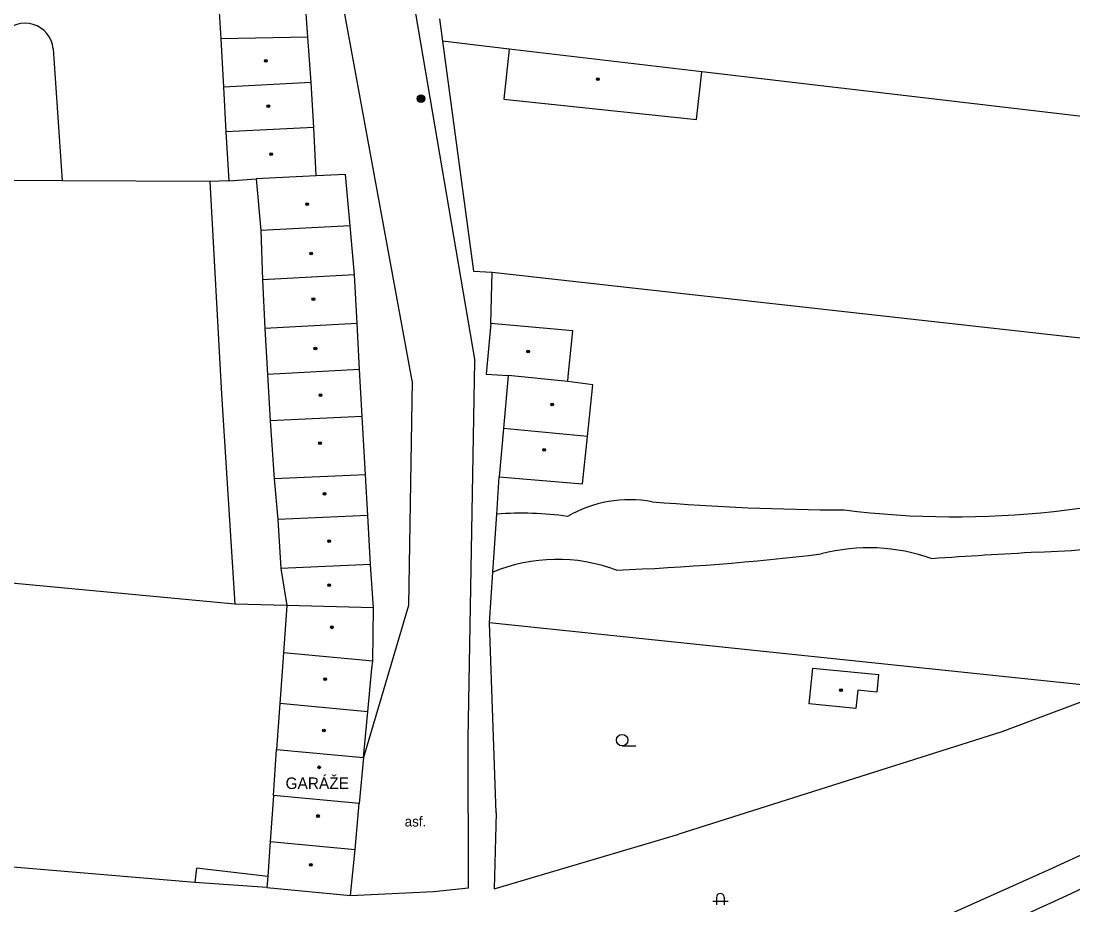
# Model space of a CAD drawing. Extents: x -596024 to -594475, y -1163820 to -1161957.
# Drawn here: x -595951 to -595882.6, y -1163179.9 to -1163122.3 of the extents above; entities that cross this region are included whole.
import ezdxf

# ---------------------------------------------------------------- set-up
doc = ezdxf.new("R2010")
doc.units = 0
for name, color, linetype in [('Level 10', 7, 'Continuous'), ('Level 11', 7, 'Continuous'), ('Level 25', 7, 'Continuous'), ('Level 36', 7, 'Continuous'), ('Level 39', 7, 'Continuous'), ('Level 40', 7, 'Continuous'), ('Level 41', 7, 'Continuous'), ('Level 5', 7, 'Continuous'), ('Level 7', 7, 'Continuous')]:
    doc.layers.add(name, color=color, linetype=linetype)

msp = doc.modelspace()

# ---------------------------------------------------------------- linework, layer by layer
at = {"layer": 'Level 10'}
for points in [[(-595925.56, -1163145.76), (-595930.74, -1163117.5)], [(-595929.58, -1163179.24), (-595924.17, -1163178.97), (-595921.89, -1163178.75), (-595921.92, -1163169.04), (-595921.49, -1163144.47)], [(-595925.56, -1163145.76), (-595925.81, -1163160.38), (-595928.73, -1163170.27)]]:
    msp.add_lwpolyline(points, dxfattribs=at)
at = {"layer": 'Level 11'}
for points in [[(-595733.15, -1163057.32), (-595759.5, -1163089.99), (-595778.37, -1163109.17), (-595795.84, -1163125.04), (-595814.68, -1163140.46), (-595836.38, -1163155.41), (-595857.69, -1163167.34), (-595883.05, -1163179.29), (-595896.6, -1163185.46), (-595919.59, -1163194.75), (-595919.36, -1163195.51)], [(-595920.12, -1163192.61), (-595897.38, -1163183.5), (-595884.17, -1163177.56), (-595867.38, -1163169.87), (-595837.49, -1163153.6), (-595815.9, -1163138.63), (-595797.14, -1163123.28), (-595781.78, -1163109.18), (-595766.48, -1163093.71), (-595763.38, -1163090.58), (-595762.22, -1163089.18), (-595761.3, -1163088.06)], [(-595925.77, -1163119.3), (-595921.49, -1163144.47)], [(-595923.78, -1163122.2), (-595923.58, -1163123.66), (-595921.57, -1163138.62), (-595920.36, -1163138.68)], [(-595948.92, -1163124.15), (-595948.33, -1163132.74)], [(-595856.82, -1163131.52), (-595871.99, -1163129.73), (-595880.33, -1163128.75), (-595906.73, -1163125.64), (-595919.26, -1163124.17), (-595923.58, -1163123.66)], [(-595919.26, -1163124.17), (-595919.6, -1163127.42), (-595907.06, -1163128.76), (-595906.73, -1163125.64)], [(-595920.36, -1163138.68), (-595849.07, -1163146.65), (-595837.48, -1163146.72)], [(-595879.71, -1163165.77), (-595920.53, -1163161.49)], [(-595920.1, -1163173.87), (-595920.22, -1163178.81), (-595908.22, -1163175.26)]]:
    msp.add_lwpolyline(points, dxfattribs=at)
for centre, radius, start, end in [((-595950.742, -1163124.316), 1.83, 5.21471, 140.80364), ((-595890.23, -1163096.703), 57.901, 262.81706, 289.89133), ((-595911.417, -1163161.507), 8.021, 79.53376, 120.26819), ((-595896.955, -1162994.59), 159.561, 265.3251, 269.81525), ((-595918.424, -1163174.864), 20.5, 81.68697, 94.57767), ((-595889.494, -1163056.561), 100.456, 272.63844, 280.63793), ((-595918.739, -1162992.496), 165.7, 272.23405, 276.85912), ((-595895.87, -1163168.881), 12.264, 70.36704, 104.54335), ((-595866.178, -1163519.66), 363.232, 92.94973, 94.03701), ((-595916.131, -1163168.287), 10.918, 69.34866, 112.50633)]:
    msp.add_arc(centre, radius, start, end, dxfattribs=at)
at = {"layer": 'Level 25'}
for radius in [0.25, 0.2, 0.15, 0.1, 0.05]:
    msp.add_circle((-595924.99, -1163127.4), radius, dxfattribs=at)
at = {"layer": 'Level 36'}
for p, q in [((-595911.9, -1163169.505), (-595911.025, -1163169.505)), ((-595906.016, -1163179.606), (-595905.016, -1163179.606)), ((-595905.766, -1163179.356), (-595905.766, -1163179.856)), ((-595905.266, -1163179.356), (-595905.266, -1163179.856))]:
    msp.add_line(p, q, dxfattribs=at)
msp.add_circle((-595911.9, -1163169.13), 0.375, dxfattribs=at)
msp.add_arc((-595905.516, -1163179.356), 0.25, 0, 180, dxfattribs=at)
at = {"layer": 'Level 39'}
for centre, radius in [((-595935.09, -1163124.93), 0.09), ((-595935.09, -1163124.93), 0.0398), ((-595913.48, -1163126.13), 0.09), ((-595913.48, -1163126.13), 0.0398), ((-595934.92, -1163127.88), 0.09), ((-595934.92, -1163127.88), 0.0398), ((-595934.74, -1163131.01), 0.09), ((-595934.74, -1163131.01), 0.0398), ((-595932.39, -1163134.26), 0.09), ((-595932.39, -1163134.26), 0.0398), ((-595932.13, -1163137.47), 0.09), ((-595932.13, -1163137.47), 0.0398), ((-595931.99, -1163140.44), 0.09), ((-595931.99, -1163140.44), 0.0398), ((-595931.86, -1163143.65), 0.09), ((-595931.86, -1163143.65), 0.0398), ((-595918.02, -1163143.84), 0.09), ((-595918.02, -1163143.84), 0.0398), ((-595931.52, -1163146.69), 0.09), ((-595931.52, -1163146.69), 0.0398), ((-595916.46, -1163147.29), 0.09), ((-595916.46, -1163147.29), 0.0398), ((-595931.56, -1163149.81), 0.09), ((-595931.56, -1163149.81), 0.0398), ((-595916.97, -1163150.24), 0.09), ((-595916.97, -1163150.24), 0.0398), ((-595931.26, -1163153.11), 0.09), ((-595931.26, -1163153.11), 0.0398), ((-595930.96, -1163156.19), 0.09), ((-595930.96, -1163156.19), 0.0398), ((-595930.96, -1163159.05), 0.09), ((-595930.96, -1163159.05), 0.0398), ((-595930.79, -1163161.79), 0.09), ((-595930.79, -1163161.79), 0.0398), ((-595931.22, -1163165.17), 0.09), ((-595931.22, -1163165.17), 0.0398), ((-595897.67, -1163165.88), 0.09), ((-595897.67, -1163165.88), 0.0398), ((-595931.31, -1163168.51), 0.09), ((-595931.31, -1163168.51), 0.0398), ((-595931.61, -1163170.9), 0.09), ((-595931.61, -1163170.9), 0.0398), ((-595931.69, -1163174.07), 0.09), ((-595931.69, -1163174.07), 0.0398), ((-595932.16, -1163177.24), 0.09), ((-595932.16, -1163177.24), 0.0398)]:
    msp.add_circle(centre, radius, dxfattribs=at)
at = {"layer": 'Level 5'}
for points in [[(-595938.19, -1163120.71), (-595938.02, -1163123.5)], [(-595932.35, -1163123.39), (-595932.55, -1163120.59)], [(-595932.35, -1163123.39), (-595938.02, -1163123.5)], [(-595938.02, -1163123.5), (-595937.84, -1163126.65)], [(-595932.13, -1163126.34), (-595932.35, -1163123.39)], [(-595932.13, -1163126.34), (-595937.84, -1163126.65)], [(-595937.84, -1163126.65), (-595937.68, -1163129.56)], [(-595931.97, -1163129.26), (-595932.13, -1163126.34)], [(-595931.97, -1163129.26), (-595937.68, -1163129.56)], [(-595937.68, -1163129.56), (-595937.5, -1163132.73)], [(-595931.81, -1163132.41), (-595931.97, -1163129.26)], [(-595931.81, -1163132.41), (-595935.71, -1163132.6)], [(-595929.89, -1163132.32), (-595931.81, -1163132.41)], [(-595929.6, -1163135.67), (-595929.89, -1163132.32)], [(-595937.5, -1163132.73), (-595935.71, -1163132.6)], [(-595935.71, -1163132.6), (-595935.41, -1163135.98)], [(-595929.6, -1163135.67), (-595935.41, -1163135.98)], [(-595929.32, -1163138.86), (-595929.6, -1163135.67)], [(-595935.41, -1163135.98), (-595935.31, -1163139.19)], [(-595929.32, -1163138.86), (-595935.31, -1163139.19)], [(-595935.31, -1163139.19), (-595935.14, -1163142.34)], [(-595929.14, -1163142.02), (-595929.32, -1163138.86)], [(-595929.14, -1163142.02), (-595935.14, -1163142.34)], [(-595928.98, -1163145.01), (-595929.14, -1163142.02)], [(-595920.45, -1163142.03), (-595920.76, -1163145.31)], [(-595915.11, -1163142.49), (-595920.45, -1163142.03)], [(-595935.14, -1163142.34), (-595934.97, -1163145.34)], [(-595915.41, -1163145.47), (-595915.11, -1163142.49)], [(-595928.98, -1163145.01), (-595934.97, -1163145.34)], [(-595934.97, -1163145.34), (-595934.8, -1163148.35)], [(-595928.81, -1163148.08), (-595928.98, -1163145.01)], [(-595920.76, -1163145.31), (-595919.32, -1163145.4)], [(-595919.32, -1163145.4), (-595919.62, -1163148.86)], [(-595915.44, -1163145.8), (-595919.32, -1163145.4)], [(-595915.44, -1163145.8), (-595915.41, -1163145.47)], [(-595913.82, -1163146.01), (-595915.44, -1163145.8)], [(-595914.16, -1163149.37), (-595913.82, -1163146.01)], [(-595928.81, -1163148.08), (-595934.8, -1163148.35)], [(-595928.6, -1163151.87), (-595928.81, -1163148.08)], [(-595934.8, -1163148.35), (-595934.54, -1163152.14)], [(-595919.62, -1163148.86), (-595919.9, -1163152.01)], [(-595914.16, -1163149.37), (-595919.62, -1163148.86)], [(-595914.48, -1163152.46), (-595914.16, -1163149.37)], [(-595928.6, -1163151.87), (-595934.54, -1163152.14)], [(-595934.54, -1163152.14), (-595934.3, -1163154.78)], [(-595928.45, -1163154.51), (-595928.6, -1163151.87)], [(-595919.9, -1163152.01), (-595914.48, -1163152.46)], [(-595928.45, -1163154.51), (-595934.3, -1163154.78)], [(-595934.3, -1163154.78), (-595934.11, -1163157.97)], [(-595928.28, -1163157.7), (-595928.45, -1163154.51)], [(-595928.28, -1163157.7), (-595934.11, -1163157.97)], [(-595928.09, -1163160.53), (-595928.28, -1163157.7)], [(-595934.11, -1163157.97), (-595933.72, -1163160.38)], [(-595933.72, -1163160.38), (-595933.94, -1163163.46)], [(-595928.09, -1163160.53), (-595933.72, -1163160.38)], [(-595928.13, -1163164), (-595928.09, -1163160.53)], [(-595933.94, -1163163.46), (-595934.17, -1163166.75)], [(-595928.13, -1163164), (-595933.94, -1163163.46)], [(-595928.45, -1163167.29), (-595928.18, -1163164.47)], [(-595928.18, -1163164.47), (-595928.13, -1163164)], [(-595899.74, -1163166.78), (-595899.51, -1163164.44)], [(-595899.51, -1163164.44), (-595895.23, -1163164.86)], [(-595895.23, -1163164.86), (-595895.34, -1163166.01)], [(-595896.58, -1163165.89), (-595896.7, -1163167.08)], [(-595895.34, -1163166.01), (-595896.58, -1163165.89)], [(-595934.17, -1163166.75), (-595934.38, -1163169.74)], [(-595928.45, -1163167.29), (-595934.17, -1163166.75)], [(-595928.73, -1163170.27), (-595928.45, -1163167.29)], [(-595896.7, -1163167.08), (-595899.74, -1163166.78)], [(-595934.59, -1163172.74), (-595934.38, -1163169.74)], [(-595934.38, -1163169.74), (-595928.73, -1163170.27)], [(-595928.73, -1163170.27), (-595929.02, -1163173.26)], [(-595934.59, -1163172.74), (-595934.8, -1163175.73)], [(-595929.02, -1163173.26), (-595934.59, -1163172.74)], [(-595929.27, -1163176.25), (-595929.02, -1163173.26)], [(-595934.8, -1163175.73), (-595934.96, -1163178.01)], [(-595934.8, -1163175.73), (-595929.27, -1163176.25)], [(-595929.58, -1163179.24), (-595929.27, -1163176.25)], [(-595934.96, -1163178.01), (-595935.01, -1163178.73)], [(-595935.01, -1163178.73), (-595929.58, -1163179.24)]]:
    msp.add_lwpolyline(points, dxfattribs=at)
at = {"layer": 'Level 7'}
for points in [[(-595938.73, -1163132.78), (-595948.33, -1163132.74), (-595969.18, -1163132.66), (-595972.57, -1163132.62), (-595981.36, -1163131.82)], [(-595937.5, -1163132.73), (-595938.73, -1163132.78)], [(-595938.73, -1163132.78), (-595937.97, -1163146.62), (-595937.1, -1163160.29)], [(-595920.45, -1163142.03), (-595920.36, -1163138.68)], [(-595920.53, -1163161.49), (-595920.31, -1163158.2), (-595920.06, -1163154.43), (-595919.9, -1163152.01)], [(-595939.7, -1163178.39), (-595960.31, -1163176.67), (-595972.39, -1163175.86), (-595974.56, -1163158.82), (-595974.96, -1163156.95)], [(-595937.1, -1163160.29), (-595966.88, -1163157.48), (-595974.96, -1163156.95)], [(-595933.72, -1163160.38), (-595937.1, -1163160.29)], [(-595920.1, -1163173.87), (-595920.53, -1163161.49)], [(-595879.71, -1163165.77), (-595887.21, -1163168.6), (-595908.22, -1163175.26)], [(-595934.96, -1163178.01), (-595939.59, -1163177.47), (-595939.7, -1163178.39)], [(-595935.01, -1163178.73), (-595939.7, -1163178.39)]]:
    msp.add_lwpolyline(points, dxfattribs=at)

# ---------------------------------------------------------------- texts
at = {"layer": 'Level 40'}
msp.add_text('asf.', height=0.65, dxfattribs=at).set_placement((-595926.05, -1163174.75))
at = {"layer": 'Level 41'}
msp.add_text('GARÁŽE', height=0.75, dxfattribs=at).set_placement((-595933.8, -1163172.31))

doc.saveas('drawing.dxf')
